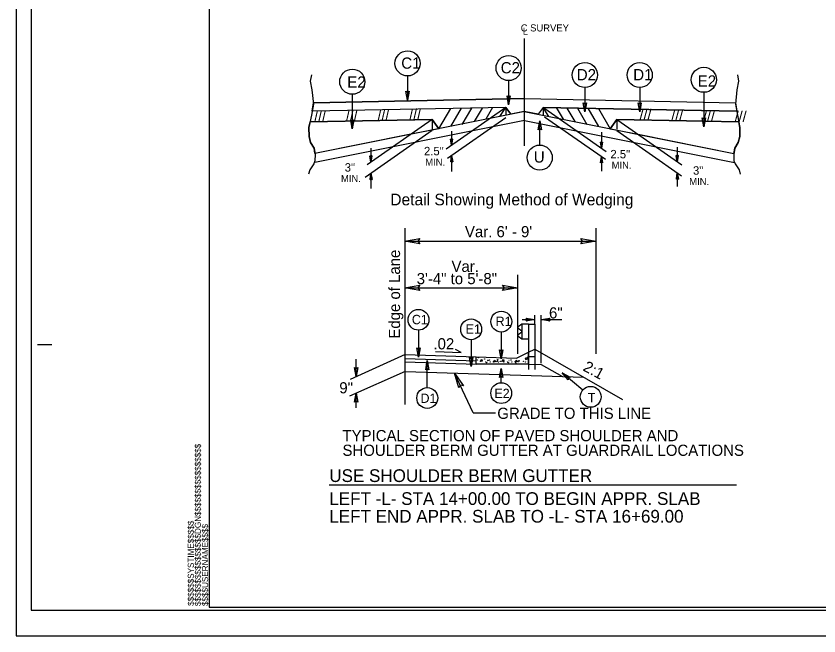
# Model space of a CAD drawing. Extents: x 573693 to 575619, y -55388 to -54288.
# Drawn here: x 573693 to 574388, y -55388 to -54852 of the extents above; entities that cross this region are included whole.
import ezdxf

# ---------------------------------------------------------------- set-up
doc = ezdxf.new("R2010")
doc.units = 0
for name, color, linetype in [('Default', 7, 'Continuous'), ('Prop Dimension', 7, 'Continuous'), ('Sheet Border Standard 30in CELL', 7, 'Continuous'), ('Sheet Cutting Line CELL', 7, 'Continuous'), ('Sheet Plot Border Inside CELL', 7, 'Continuous'), ('Sheet Plot Border Outside CELL', 7, 'Continuous'), ('Typical Curb CELL', 7, 'Continuous'), ('Typical Detail Wedge2 CELL', 7, 'Continuous'), ('Typical Guardrail CELL', 7, 'Continuous'), ('Typical ID Circle CELL', 7, 'Continuous'), ('Typical Terminator CELL', 7, 'Continuous'), ('Typical Text Centerline CELL', 7, 'Continuous'), ('Typical Text General CELL', 7, 'Continuous'), ('Typical Text Grade Point CELL', 7, 'Continuous'), ('Typical Text ID Circle CELL', 7, 'Continuous')]:
    doc.layers.add(name, color=color, linetype=linetype)

msp = doc.modelspace()

# ---------------------------------------------------------------- linework, layer by layer
at = {"layer": 'Default'}
for p, q in [((574029.52, -55187.83), (574029.49, -55035.28)), ((574194.7, -55144.04), (574194.68, -55035.25)), ((574029.06, -55046.48), (574194.68, -55046.48)), ((574126.98, -55144.06), (574126.97, -55075.73)), ((574029.5, -55086.92), (574126.97, -55086.92)), ((574141.77, -55118.36), (574141.77, -55110.73)), ((574147.37, -55152.07), (574147.37, -55110.73)), ((574130.81, -55114.49), (574141.77, -55114.49)), ((574147.37, -55114.49), (574165.21, -55114.49)), ((574078.02, -55142.99), (574073.04, -55140.31)), ((574136.21, -55142.78), (574141.77, -55140)), ((574141.77, -55140), (574217.57, -55183.57)), ((574029.51, -55144.67), (573982.03, -55166.18)), ((574029.51, -55144.67), (574091.07, -55146.69)), ((574055.74, -55142.12), (574078.02, -55142.99)), ((574029.52, -55148.13), (574090.91, -55150.14)), ((574029.52, -55150.92), (574090.91, -55152.93)), ((574136.21, -55152.93), (574147.33, -55153.29)), ((574147.33, -55153.29), (574165.64, -55163.82)), ((574029.46, -55159.36), (573981.55, -55180.86)), ((574029.46, -55159.36), (574184.28, -55164.43)), ((574088.32, -55195.14), (574072.32, -55160.77)), ((574088.32, -55195.14), (574107.8, -55195.14))]:
    msp.add_line(p, q, dxfattribs=at)
at = {"layer": 'Prop Dimension'}
msp.add_line((573963.94, -55257.55), (574316.19, -55257.55), dxfattribs=at)
at = {"layer": 'Sheet Border Standard 30in CELL'}
msp.add_line((573711.47, -55135.89), (573723.97, -55135.89), dxfattribs=at)
msp.add_lwpolyline([(575359.97, -54313.39), (573859.97, -54313.39), (573859.97, -55363.39), (575359.97, -55363.39)], close=True, dxfattribs=at)
at = {"layer": 'Sheet Cutting Line CELL'}
for p, q in [((573692.97, -54288.39), (573692.97, -55388.39)), ((573692.97, -55388.39), (575376.97, -55388.39))]:
    msp.add_line(p, q, dxfattribs=at)
at = {"layer": 'Sheet Plot Border Inside CELL'}
msp.add_lwpolyline([(575372.47, -54310.84), (573705.97, -54310.84), (573705.97, -55365.94), (575372.47, -55365.94)], close=True, dxfattribs=at)
at = {"layer": 'Sheet Plot Border Outside CELL'}
msp.add_lwpolyline([(575376.97, -54288.39), (573692.97, -54288.39), (573692.97, -55388.39), (575376.97, -55388.39)], close=True, dxfattribs=at)
at = {"layer": 'Typical Curb CELL'}
for p, q in [((574090.91, -55146.68), (574090.91, -55146.68)), ((574090.91, -55152.93), (574090.91, -55146.84)), ((574091.07, -55146.69), (574125.9, -55147.93)), ((574125.9, -55147.93), (574136.21, -55142.78)), ((574133.35, -55147.78), (574133.6, -55149.14)), ((574135.67, -55148.45), (574133.35, -55147.78)), ((574136.21, -55152.93), (574136.21, -55142.78)), ((574136.21, -55152.93), (574090.91, -55152.93)), ((574094.47, -55150.65), (574095.77, -55148.86)), ((574096.28, -55150.56), (574094.47, -55150.65)), ((574095.77, -55148.86), (574096.28, -55150.56)), ((574105.95, -55151.42), (574106.89, -55149.7)), ((574108.44, -55150.82), (574105.95, -55151.42)), ((574106.89, -55149.7), (574108.44, -55150.82)), ((574113.22, -55150.65), (574114.5, -55148.86)), ((574115.01, -55150.56), (574113.22, -55150.65)), ((574114.5, -55148.86), (574115.01, -55150.56)), ((574124.68, -55151.42), (574125.62, -55149.7)), ((574127.17, -55150.82), (574124.68, -55151.42)), ((574125.62, -55149.7), (574127.17, -55150.82)), ((574133.6, -55149.14), (574135.67, -55148.45))]:
    msp.add_line(p, q, dxfattribs=at)
for centre in [(574092.82, -55147.47), (574135.24, -55147.17), (574092.26, -55149.35), (574098.33, -55148.59), (574099.22, -55151.26), (574100.06, -55151.78), (574100.56, -55149.88), (574101.69, -55149.91), (574102.44, -55149.45), (574103.15, -55151.18), (574106.06, -55150.59), (574109.14, -55150.83), (574109.4, -55150.08), (574109.55, -55149.19), (574110.4, -55151.33), (574111.85, -55150.65), (574113.25, -55150.51), (574115.05, -55151.26), (574117.96, -55151.26), (574118.8, -55151.78), (574119.29, -55149.88), (574121.18, -55149.45), (574121.88, -55151.18), (574124.8, -55150.59), (574125.22, -55152.12), (574127.88, -55150.83), (574128.13, -55150.08), (574131.99, -55150.51), (574133.79, -55151.26)]:
    msp.add_circle(centre, 0.12, dxfattribs=at)
msp.add_arc((574091.06, -55146.84), 0.156, 87.95199, 180, dxfattribs=at)
at = {"layer": 'Typical Detail Wedge2 CELL'}
for p, q in [((574132.78, -54964.13), (574132.78, -54871.08)), ((574132.78, -54964.13), (574132.78, -54900.58)), ((574132.77, -54923.02), (573950.15, -54926.67)), ((573950.15, -54926.67), (574132.77, -54923.02)), ((574132.77, -54923.02), (574315.4, -54926.67)), ((574132.79, -54923.02), (574315.4, -54926.67)), ((573949.11, -54934.01), (573950.15, -54926.67)), ((574116.75, -54930.66), (573949.11, -54934.01)), ((574116.75, -54930.66), (573949.11, -54934.01)), ((574068.86, -54931.62), (574058.48, -54949.4)), ((574116.54, -54930.79), (574065.09, -54966.83)), ((574077.97, -54931.43), (574068.78, -54947.2)), ((574086.99, -54931.26), (574078.74, -54945.39)), ((574096.08, -54931.28), (574089.24, -54942.98)), ((574105.24, -54930.81), (574099.29, -54941.02)), ((574111.56, -54938.47), (574116.52, -54930.73)), ((574116.52, -54930.73), (574116.52, -54937.09)), ((574120.85, -54936.67), (574116.75, -54930.66)), ((574116.75, -54930.85), (574120.85, -54936.67)), ((574148.93, -54930.66), (574144.69, -54936.67)), ((574148.93, -54930.66), (574144.69, -54936.67)), ((574148.66, -54930.79), (574148.92, -54930.81)), ((574148.93, -54930.66), (574316.45, -54934.01)), ((574316.45, -54934.01), (574148.93, -54930.66)), ((574153.99, -54938.47), (574149.04, -54930.73)), ((574149.04, -54930.73), (574149.04, -54937.73)), ((574150.33, -54931.63), (574203.34, -54968.76)), ((574160.3, -54930.81), (574166.27, -54941.02)), ((574169.47, -54931.28), (574176.3, -54942.98)), ((574178.56, -54931.26), (574186.81, -54945.39)), ((574187.58, -54931.43), (574196.77, -54947.2)), ((574196.71, -54931.62), (574206.92, -54949.14)), ((574315.4, -54926.67), (574316.45, -54934.01)), ((574133.05, -54934.25), (573951.52, -54970.57)), ((574132.5, -54934.25), (574120.85, -54936.67)), ((574132.5, -54934.25), (574314.04, -54970.57)), ((574144.69, -54936.67), (574132.5, -54934.25)), ((574150.25, -54938.85), (574202.75, -54975.6)), ((574052.88, -54941.09), (573947.33, -54943.21)), ((573947.33, -54943.21), (574052.88, -54941.09)), ((574132.7, -54942.07), (573951.46, -54978.32)), ((574052.88, -54941.09), (573996.84, -54980.34)), ((574058.62, -54949.16), (574052.88, -54941.09)), ((574052.88, -54941.09), (574052.88, -54950.3)), ((574052.88, -54941.09), (574058.61, -54949.14)), ((574116.66, -54939.6), (574066.31, -54974.85)), ((574132.84, -54942.07), (574314.51, -54978.41)), ((574212.66, -54941.09), (574206.92, -54949.14)), ((574206.94, -54949.14), (574212.66, -54941.09)), ((574212.66, -54941.09), (574318.22, -54943.21)), ((574212.66, -54941.09), (574212.66, -54949.65)), ((574287.95, -54942.6), (574212.66, -54941.09)), ((574213.52, -54941.69), (574268.8, -54980.4)), ((574318.22, -54943.21), (574287.95, -54942.6)), ((574052.84, -54950.59), (573994.9, -54991.36)), ((574052.88, -54950.29), (574034.5, -54953.97)), ((574058.61, -54949.14), (574052.88, -54950.29)), ((574069.77, -54951.3), (574069.77, -54963.54)), ((574199.46, -54952.01), (574199.46, -54966.04)), ((574206.92, -54949.14), (574231.05, -54953.97)), ((574212.66, -54950.77), (574268.7, -54990.02)), ((574034.5, -54953.97), (573951.52, -54970.57)), ((574069.77, -54963.54), (574068.83, -54958.18)), ((574069.77, -54958.88), (574068.83, -54958.18)), ((574069.77, -54963.54), (574068.96, -54958.28)), ((574069.1, -54958.38), (574069.77, -54963.54)), ((574069.77, -54963.54), (574069.23, -54958.47)), ((574069.37, -54958.57), (574069.77, -54963.54)), ((574069.77, -54963.54), (574069.51, -54958.67)), ((574069.64, -54958.78), (574069.77, -54963.54)), ((574069.77, -54963.54), (574070.73, -54958.18)), ((574070.73, -54958.18), (574069.77, -54958.88)), ((574070.59, -54958.28), (574069.77, -54963.54)), ((574069.77, -54963.54), (574070.45, -54958.38)), ((574070.31, -54958.47), (574069.77, -54963.54)), ((574069.77, -54963.54), (574070.18, -54958.57)), ((574070.04, -54958.67), (574069.77, -54963.54)), ((574069.77, -54963.54), (574069.91, -54958.78)), ((574069.77, -54958.88), (574069.77, -54963.54)), ((574231.05, -54953.97), (574314.04, -54970.57)), ((573999.99, -54965.93), (573999.99, -54978.14)), ((574199.46, -54966.04), (574198.52, -54960.67)), ((574199.46, -54961.37), (574198.52, -54960.67)), ((574199.46, -54966.04), (574198.65, -54960.77)), ((574198.79, -54960.87), (574199.46, -54966.04)), ((574199.46, -54966.04), (574198.92, -54960.97)), ((574199.06, -54961.07), (574199.46, -54966.04)), ((574199.46, -54966.04), (574199.19, -54961.17)), ((574199.32, -54961.27), (574199.46, -54966.04)), ((574199.46, -54966.04), (574200.41, -54960.67)), ((574200.41, -54960.67), (574199.46, -54961.37)), ((574200.27, -54960.77), (574199.46, -54966.04)), ((574199.46, -54966.04), (574200.14, -54960.87)), ((574200, -54960.97), (574199.46, -54966.04)), ((574199.46, -54966.04), (574199.87, -54961.07)), ((574199.73, -54961.17), (574199.46, -54966.04)), ((574199.46, -54966.04), (574199.6, -54961.27)), ((574199.46, -54961.37), (574199.46, -54966.04)), ((574265, -54965.05), (574265, -54977.74)), ((573999.99, -54978.14), (573999.04, -54972.77)), ((573999.99, -54973.46), (573999.04, -54972.77)), ((573999.99, -54978.14), (573999.17, -54972.86)), ((573999.32, -54972.97), (573999.99, -54978.14)), ((573999.99, -54978.14), (573999.45, -54973.06)), ((573999.59, -54973.16), (573999.99, -54978.14)), ((573999.99, -54978.14), (573999.72, -54973.26)), ((573999.86, -54973.36), (573999.99, -54978.14)), ((573999.99, -54978.14), (574000.94, -54972.77)), ((574000.94, -54972.77), (573999.99, -54973.46)), ((574000.8, -54972.86), (573999.99, -54978.14)), ((573999.99, -54978.14), (574000.67, -54972.97)), ((574000.54, -54973.06), (573999.99, -54978.14)), ((573999.99, -54978.14), (574000.39, -54973.16)), ((574000.27, -54973.26), (573999.99, -54978.14)), ((573999.99, -54978.14), (574000.13, -54973.36)), ((573999.99, -54973.46), (573999.99, -54978.14)), ((574069.77, -54972.43), (574068.83, -54977.8)), ((574068.96, -54977.7), (574069.77, -54972.43)), ((574069.77, -54972.43), (574069.1, -54977.6)), ((574069.23, -54977.49), (574069.77, -54972.43)), ((574069.77, -54972.43), (574069.37, -54977.4)), ((574069.51, -54977.31), (574069.77, -54972.43)), ((574069.77, -54972.43), (574069.64, -54977.2)), ((574069.77, -54972.43), (574069.77, -54986.21)), ((574069.77, -54972.43), (574070.73, -54977.8)), ((574069.77, -54977.1), (574069.77, -54972.43)), ((574069.91, -54977.2), (574069.77, -54972.43)), ((574069.77, -54972.43), (574070.04, -54977.31)), ((574070.18, -54977.4), (574069.77, -54972.43)), ((574069.77, -54972.43), (574070.31, -54977.49)), ((574070.45, -54977.6), (574069.77, -54972.43)), ((574069.77, -54972.43), (574070.59, -54977.7)), ((574199.46, -54973.3), (574198.52, -54978.68)), ((574198.65, -54978.57), (574199.46, -54973.3)), ((574199.46, -54973.3), (574198.79, -54978.47)), ((574198.92, -54978.37), (574199.46, -54973.3)), ((574199.46, -54973.3), (574199.06, -54978.27)), ((574199.19, -54978.18), (574199.46, -54973.3)), ((574199.46, -54973.3), (574199.32, -54978.08)), ((574199.46, -54973.3), (574199.46, -54985.86)), ((574199.46, -54973.3), (574200.41, -54978.68)), ((574199.46, -54977.98), (574199.46, -54973.3)), ((574199.6, -54978.08), (574199.46, -54973.3)), ((574199.46, -54973.3), (574199.73, -54978.18)), ((574199.87, -54978.27), (574199.46, -54973.3)), ((574199.46, -54973.3), (574200, -54978.37)), ((574200.14, -54978.47), (574199.46, -54973.3)), ((574199.46, -54973.3), (574200.27, -54978.57)), ((574265, -54977.74), (574264.05, -54972.37)), ((574265, -54973.06), (574264.05, -54972.37)), ((574265, -54977.74), (574264.19, -54972.47)), ((574264.32, -54972.57), (574265, -54977.74)), ((574265, -54977.74), (574264.45, -54972.66)), ((574264.59, -54972.77), (574265, -54977.74)), ((574265, -54977.74), (574264.72, -54972.86)), ((574264.86, -54972.97), (574265, -54977.74)), ((574265, -54977.74), (574265.94, -54972.37)), ((574265.94, -54972.37), (574265, -54973.06)), ((574265.8, -54972.47), (574265, -54977.74)), ((574265, -54977.74), (574265.67, -54972.57)), ((574265.53, -54972.66), (574265, -54977.74)), ((574265, -54977.74), (574265.4, -54972.77)), ((574265.27, -54972.86), (574265, -54977.74)), ((574265, -54977.74), (574265.13, -54972.97)), ((574265, -54973.06), (574265, -54977.74)), ((574068.83, -54977.8), (574069.77, -54977.1)), ((574069.77, -54977.1), (574070.73, -54977.8)), ((574198.52, -54978.68), (574199.46, -54977.98)), ((574199.46, -54977.98), (574200.41, -54978.68)), ((573999.99, -54987.79), (573999.04, -54993.16)), ((573999.19, -54993.06), (573999.99, -54987.79)), ((573999.99, -54987.79), (573999.32, -54992.96)), ((573999.45, -54992.86), (573999.99, -54987.79)), ((573999.99, -54987.79), (573999.59, -54992.76)), ((573999.72, -54992.67), (573999.99, -54987.79)), ((573999.99, -54987.79), (573999.86, -54992.57)), ((573999.99, -54987.79), (573999.99, -55000.84)), ((573999.99, -54987.79), (574000.94, -54993.16)), ((573999.99, -54992.47), (573999.99, -54987.79)), ((574000.13, -54992.57), (573999.99, -54987.79)), ((573999.99, -54987.79), (574000.27, -54992.67)), ((574000.4, -54992.76), (573999.99, -54987.79)), ((573999.99, -54987.79), (574000.54, -54992.86)), ((574000.67, -54992.96), (573999.99, -54987.79)), ((573999.99, -54987.79), (574000.8, -54993.06)), ((574265, -54987.42), (574264.05, -54992.79)), ((574264.19, -54992.69), (574265, -54987.42)), ((574265, -54987.42), (574264.32, -54992.59)), ((574264.45, -54992.49), (574265, -54987.42)), ((574265, -54987.42), (574264.59, -54992.38)), ((574264.72, -54992.28), (574265, -54987.42)), ((574265, -54987.42), (574264.86, -54992.19)), ((574265, -54987.42), (574265, -54999.21)), ((574265, -54987.42), (574265.94, -54992.79)), ((574265, -54992.08), (574265, -54987.42)), ((574265.13, -54992.19), (574265, -54987.42)), ((574265, -54987.42), (574265.27, -54992.28)), ((574265.4, -54992.38), (574265, -54987.42)), ((574265, -54987.42), (574265.53, -54992.49)), ((574265.67, -54992.59), (574265, -54987.42)), ((574265, -54987.42), (574265.8, -54992.69)), ((573999.04, -54993.16), (573999.99, -54992.47)), ((573999.99, -54992.47), (574000.94, -54993.16)), ((574264.05, -54992.79), (574265, -54992.08)), ((574265, -54992.08), (574265.94, -54992.79))]:
    msp.add_line(p, q, dxfattribs=at)
for points in [[(573948.45, -54902.57), (573947.48, -54907.92), (573948.94, -54915.53), (573950.23, -54927.84), (573948.45, -54937.56), (573946.35, -54948.09), (573946.51, -54956.03), (573947.81, -54961.04), (573950.73, -54966.07), (573951.69, -54971.58), (573951.53, -54977.08), (573950.56, -54979.68), (573947.16, -54984.87), (573946.03, -54988.43)], [(574317.1, -54902.57), (574318.07, -54907.92), (574316.61, -54915.53), (574315.32, -54927.84), (574317.1, -54937.56), (574319.2, -54948.09), (574319.04, -54956.03), (574317.74, -54961.04), (574314.83, -54966.07), (574313.86, -54971.58), (574314.01, -54977.08), (574314.99, -54979.68), (574318.39, -54984.87), (574319.52, -54988.43)], [(573951.51, -54970.57), (573950.73, -54966.07), (573947.81, -54961.04), (573946.51, -54956.03), (573946.35, -54948.09), (573947.32, -54943.21)], [(574314.04, -54970.57), (574314.83, -54966.07), (574317.74, -54961.04), (574319.04, -54956.03), (574319.2, -54948.09), (574318.22, -54943.21)]]:
    msp.add_lwpolyline(points, dxfattribs=at)
at = {"layer": 'Typical Guardrail CELL'}
for p, q in [((574130.58, -55118.36), (574127.33, -55120.64)), ((574136.18, -55118.36), (574130.58, -55118.36)), ((574130.58, -55118.36), (574130.58, -55131.4)), ((574136.18, -55118.36), (574136.18, -55146.32)), ((574136.18, -55118.36), (574141.77, -55118.36)), ((574141.77, -55118.36), (574141.77, -55146.32)), ((574130.58, -55124.35), (574127.33, -55122.07)), ((574130.58, -55125.41), (574127.33, -55127.69)), ((574130.58, -55124.88), (574130.58, -55124.35)), ((574130.58, -55124.88), (574130.58, -55125.41)), ((574130.58, -55131.4), (574127.33, -55129.12)), ((574136.18, -55131.4), (574130.58, -55131.4)), ((574136.18, -55146.32), (574141.77, -55146.32)), ((574136.18, -55146.32), (574136.18, -55157.66)), ((574141.77, -55146.32), (574141.77, -55157.66))]:
    msp.add_line(p, q, dxfattribs=at)
for centre, start, end in [((574127.82, -55121.36), 125.00297, 235.0112), ((574127.82, -55128.41), 125.0059, 235.0366)]:
    msp.add_arc(centre, 0.874, start, end, dxfattribs=at)
at = {"layer": 'Typical ID Circle CELL'}
for p, q in [((574031.65, -54903.49), (574031.65, -54924.58)), ((574119.09, -54907.5), (574119.09, -54928.58)), ((574185.04, -54913.52), (574185.04, -54934.61)), ((574232.48, -54913.52), (574232.48, -54934.61)), ((574287.95, -54917.66), (574287.95, -54947.64)), ((573983.85, -54919.33), (573983.85, -54949.31)), ((574145.99, -54963.33), (574145.99, -54942.25)), ((574041.09, -55123.63), (574041.09, -55146.93)), ((574112.73, -55125.22), (574112.73, -55148.52)), ((574086.65, -55131.88), (574086.65, -55155.18)), ((573987.2, -55163.84), (573987.2, -55148.59)), ((574048.7, -55173.31), (574048.7, -55150.01)), ((574112.67, -55169.1), (574112.67, -55156.67)), ((574183.15, -55175.52), (574165.29, -55160.56)), ((573987.2, -55190.99), (573987.2, -55178.33))]:
    msp.add_line(p, q, dxfattribs=at)
for centre, radius in [((574031.65, -54892.62), 10.88), ((574119.09, -54896.63), 10.88), ((573983.85, -54908.46), 10.88), ((574185.04, -54902.65), 10.88), ((574232.48, -54902.65), 10.88), ((574287.95, -54906.78), 10.88), ((574145.99, -54974.2), 10.88), ((574041.09, -55114.62), 9.02), ((574112.73, -55116.21), 9.02), ((574086.65, -55122.87), 9.02), ((574048.7, -55182.32), 9.02), ((574112.67, -55178.11), 9.02), ((574190.06, -55181.31), 9.02)]:
    msp.add_circle(centre, radius, dxfattribs=at)
at = {"layer": 'Typical Terminator CELL'}
for points in [[(574033.02, -54916.67), (574031.65, -54924.58), (574030.25, -54916.62), (574031.65, -54917.63)], [(574033.02, -54916.67), (574031.65, -54924.58), (574030.25, -54916.62), (574031.65, -54917.63)], [(574120.45, -54920.68), (574119.09, -54928.58), (574117.68, -54920.63), (574119.09, -54921.64)], [(574120.45, -54920.68), (574119.09, -54928.58), (574117.68, -54920.63), (574119.09, -54921.64)], [(574186.4, -54926.7), (574185.04, -54934.61), (574183.63, -54926.65), (574185.04, -54927.66)], [(574186.4, -54926.7), (574185.04, -54934.61), (574183.63, -54926.65), (574185.04, -54927.66)], [(574233.85, -54926.7), (574232.48, -54934.61), (574231.08, -54926.65), (574232.48, -54927.66)], [(574233.85, -54926.7), (574232.48, -54934.61), (574231.08, -54926.65), (574232.48, -54927.66)], [(573985.21, -54941.4), (573983.85, -54949.31), (573982.44, -54941.36), (573983.85, -54942.37)], [(574144.63, -54950.16), (574145.99, -54942.25), (574147.4, -54950.2), (574145.99, -54949.19)], [(574144.63, -54950.16), (574145.99, -54942.25), (574147.4, -54950.2), (574145.99, -54949.19)], [(574289.31, -54939.73), (574287.95, -54947.64), (574286.54, -54939.68), (574287.95, -54940.7)], [(574042.24, -55048.75), (574029.06, -55046.48), (574042.32, -55044.14), (574040.63, -55046.48)], [(574181.5, -55044.21), (574194.68, -55046.48), (574181.43, -55048.83), (574183.11, -55046.48)], [(574042.24, -55089.19), (574029.06, -55086.92), (574042.32, -55084.58), (574040.63, -55086.92)], [(574113.79, -55084.65), (574126.97, -55086.92), (574113.71, -55089.26), (574115.4, -55086.92)], [(574134.34, -55113.32), (574141.77, -55114.49), (574134.34, -55115.92), (574135.26, -55114.59)], [(574154.78, -55115.77), (574147.37, -55114.49), (574154.82, -55113.17), (574153.87, -55114.49)], [(574042.45, -55139.02), (574041.09, -55146.93), (574039.68, -55138.98), (574041.09, -55139.99)], [(574114.09, -55140.61), (574112.73, -55148.52), (574111.32, -55140.57), (574112.73, -55141.58)], [(574088.01, -55147.27), (574086.65, -55155.18), (574085.24, -55147.23), (574086.65, -55148.24)], [(574047.34, -55157.92), (574048.7, -55150.01), (574050.11, -55157.96), (574048.7, -55156.95)], [(573988.57, -55155.93), (573987.2, -55163.84), (573985.8, -55155.89), (573987.2, -55156.9)], [(574075.94, -55173.64), (574072.32, -55160.77), (574080.14, -55171.72), (574077.3, -55171.21)], [(574111.31, -55164.58), (574112.67, -55156.67), (574114.08, -55164.62), (574112.67, -55163.61)], [(574170.65, -55166.53), (574165.29, -55160.56), (574172.4, -55164.39), (574170.74, -55164.86)], [(573985.84, -55186.05), (573987.2, -55178.14), (573988.61, -55186.09), (573987.2, -55185.08)]]:
    msp.add_lwpolyline(points, close=True, dxfattribs=at)

# ---------------------------------------------------------------- texts
at = {"layer": 'Default'}
for s, height, p in [("Var. 6' - 9'", 9.6772, (574081.28, -55043.14)), ('Var.', 9.677, (574069.65, -55073.17)), ('3\'-4" to 5\'-8"', 9.6772, (574039.55, -55083.8)), ('6"', 9.677, (574154.01, -55113.49)), ('.02', 9.677, (574054.03, -55140.23)), ('9"', 9.677, (573972.62, -55178.32)), ('GRADE TO THIS LINE', 9.6772, (574109.29, -55200.42)), ('TYPICAL SECTION OF PAVED SHOULDER AND ', 9.6772, (573975.35, -55219.75)), ('SHOULDER BERM GUTTER AT GUARDRAIL LOCATIONS', 9.6772, (573975.35, -55232.44))]:
    msp.add_text(s, height=height, dxfattribs=at).set_placement(p)
for s, height, rotation, p in [('Edge of Lane', 9.6772, 90, (574025.15, -55130.91)), ('2:1', 9.677, 331.59097, (574182.66, -55158.16))]:
    msp.add_text(s, height=height, rotation=rotation, dxfattribs=at).set_placement(p)
at = {"layer": 'Sheet Border Standard 30in CELL'}
for s, p in [('$$$$$$$$$$$$$$$$DGN$$$$$$$$$$$$$$$$', (573852.82, -55362.54)), ('$$$$$$SYSTIME$$$$$', (573846.77, -55362.34)), ('$$$$USERNAME$$$$', (573859.12, -55362.44))]:
    msp.add_text(s, height=5.25, rotation=90, dxfattribs=at).set_placement(p)
at = {"layer": 'Typical Detail Wedge2 CELL'}
for height, rotation, p in [(9.154, 1.14453, (574005.77, -54941.95)), (9.155, 1.14629, (574033.22, -54941.39)), (9.155, 358.85527, (574232.33, -54941.39)), (9.155, 358.85361, (574259.79, -54941.95)), (9.158, 1.14473, (573950.96, -54943.08)), (9.158, 1.14639, (573978.33, -54942.76)), (9.158, 358.85537, (574287.21, -54942.76)), (9.158, 358.85371, (574314.59, -54943.08))]:
    msp.add_text('/// ', height=height, rotation=rotation, dxfattribs=at).set_placement(p)
for s, height, p in [('2.5"', 7.301, (574045.86, -54972.18)), ('2.5"', 7.301, (574207.11, -54974.83)), ('3"', 7.301, (573977.3, -54986.32)), ('MIN.', 6.101, (574046.93, -54981.15)), ('MIN.', 6.101, (574208.18, -54983.8)), ('3"', 7.301, (574278.59, -54988.97)), ('MIN.', 6.101, (573974.04, -54995.3)), ('MIN.', 6.101, (574275.33, -54997.95))]:
    msp.add_text(s, height=height, dxfattribs=at).set_placement(p)
at = {"layer": 'Typical Text Centerline CELL'}
for s, height, p in [('C SURVEY ', 6.101, (574129.55, -54864.94)), ('L', 6.1, (574131.33, -54867.79))]:
    msp.add_text(s, height=height, dxfattribs=at).set_placement(p)
at = {"layer": 'Typical Text General CELL'}
msp.add_text('Detail Showing Method of Wedging', height=10.0707, dxfattribs=at).set_placement((574016.7, -55015.5))
at = {"layer": 'Typical Text Grade Point CELL'}
for s, p in [('USE SHOULDER BERM GUTTER', (573963.94, -55255.09)), ('LEFT -L- STA 14+00.00 TO BEGIN APPR. SLAB', (573963.94, -55274.95)), ('LEFT END APPR. SLAB TO -L- STA 16+69.00', (573963.94, -55290.27))]:
    msp.add_text(s, height=11.0105, dxfattribs=at).set_placement(p)
at = {"layer": 'Typical Text ID Circle CELL'}
for s, height, p in [('C1', 9.735, (574026.2, -54897.21)), ('C2', 9.735, (574112.24, -54901.23)), ('D2', 9.735, (574178.05, -54907.25)), ('D1', 9.735, (574226.89, -54907.25)), ('E2', 9.735, (573979.48, -54913.64)), ('E2', 9.735, (574282.66, -54912.71)), ('U', 9.73, (574140.86, -54978.52)), ('C1', 8.07, (574035.35, -55118.43)), ('R1', 8.07, (574107.82, -55120.02)), ('E1', 8.07, (574081.89, -55126.68))]:
    msp.add_text(s, height=height, dxfattribs=at).set_placement(p)
for s, rotation, p in [('E2', 360, (574106.76, -55182.37)), ('D1', 360, (574042.84, -55186.58)), ('T ', 0.01596, (574187.6, -55185.97))]:
    msp.add_text(s, height=8.07, rotation=rotation, dxfattribs=at).set_placement(p)

doc.saveas('drawing.dxf')
